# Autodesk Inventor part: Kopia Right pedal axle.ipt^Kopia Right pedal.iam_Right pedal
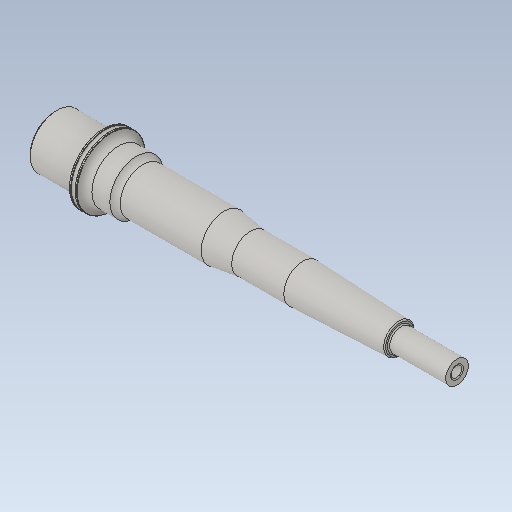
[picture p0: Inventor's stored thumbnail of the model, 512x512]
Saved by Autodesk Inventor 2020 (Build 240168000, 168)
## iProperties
Created: 2017-10
Part Number: Kopia Right pedal axle.ipt^Kopia Right pedal.iam_Right pedal
Material: solidworks materials|AISI 4130 Stal normalizowana w 870C|95
Document SubType Name: Modeling
Designer: Tomasz
Density: 7.85 g/cm^3
Appearance: 0,0,0
Sending System: SolidWorks 2017
Last Author: Tomasz
Last Saved: 2017-11-19
Author: Tomasz
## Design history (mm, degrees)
feature "Right pedal axle.ipt"
node "Bryła1"
